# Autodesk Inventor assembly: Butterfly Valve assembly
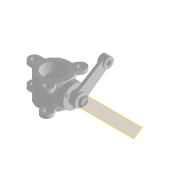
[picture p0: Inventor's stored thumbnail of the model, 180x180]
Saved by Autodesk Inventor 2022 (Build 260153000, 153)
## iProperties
Created: 2019-03
Part Number: Butterfly Valve assembly
Document SubType Name: Assembly
Designer: LENOVO-CADCIM
Author: LENOVO-CADCIM
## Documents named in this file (10)
- D:\PROJECTS_2021\Resources\Tutorial Files\c10_Inv_2022_tut\c10_tut01_Inv\Butterfly Valve\Butterfly Valve assembly.iam
- D:\PROJECTS_2021\Resources\Tutorial Files\c10_Inv_2022_tut\c10_tut01_Inv\Butterfly Valve\Body.ipt
- D:\PROJECTS_2021\Resources\Tutorial Files\c10_Inv_2022_tut\c10_tut01_Inv\Butterfly Valve\Shaft.ipt
- D:\PROJECTS_2021\Resources\Tutorial Files\c10_Inv_2022_tut\c10_tut01_Inv\Butterfly Valve\Retainer.ipt
- D:\PROJECTS_2021\Resources\Tutorial Files\c10_Inv_2022_tut\c10_tut01_Inv\Butterfly Valve\Arm.ipt
- D:\PROJECTS_2021\Resources\Tutorial Files\c10_Inv_2022_tut\c10_tut01_Inv\Butterfly Valve\Plate.ipt
- D:\PROJECTS_2021\Resources\Tutorial Files\c10_Inv_2022_tut\c10_tut01_Inv\Butterfly Valve\scew1.ipt
- D:\PROJECTS_2021\Resources\Tutorial Files\c10_Inv_2022_tut\c10_tut01_Inv\Butterfly Valve\Screw.ipt
- D:\PROJECTS_2021\Resources\Tutorial Files\c10_Inv_2022_tut\c10_tut01_Inv\Butterfly Valve\Parallel key.ipt
- D:\PROJECTS_2021\Resources\Tutorial Files\c10_Inv_2022_tut\c10_tut01_Inv\Butterfly Valve\Nut.ipt
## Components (12 placed, 9 different names)
1. Body:1 — Insert:1, Insert:2, Mate:1, Angle:4, Angle:5
2. Shaft:1 — Insert:1, Insert:3, Insert:4, Mate:3, Insert:11, Angle:5
3. Retainer:1 — Insert:2, Mate:1, Insert:7, Insert:8, Insert:9, Insert:10
4. Arm:1 — Insert:10, Mate:2, Flush:1
5. Plate:1 — Insert:3, Insert:4, Insert:5, Insert:6
6. scew1:1 — Insert:5
7. scew1:2 — Insert:6
8. Screw:1 — Insert:7
9. Screw:2 — Insert:8
10. Screw:3 — Insert:9
11. Parallel key:1 — Mate:2, Mate:3, Flush:1
12. Nut:1 — Insert:11, Angle:4
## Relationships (17: Insert 11, Mate 3, Angle 2, Flush 1)
- Insert:1: Body:1 ↔ Shaft:1
- Insert:2: Body:1 ↔ Retainer:1
- Mate:1: Body:1 ↔ Retainer:1
- Insert:3: Shaft:1 ↔ Plate:1
- Insert:4: Shaft:1 ↔ Plate:1
- Insert:5: Plate:1 ↔ scew1:1
- Insert:6: Plate:1 ↔ scew1:2
- Insert:7: Retainer:1 ↔ Screw:1
- Insert:8: Retainer:1 ↔ Screw:2
- Insert:9: Retainer:1 ↔ Screw:3
- Insert:10: Retainer:1 ↔ Arm:1
- Mate:2: Arm:1 ↔ Parallel key:1
- Mate:3: Shaft:1 ↔ Parallel key:1
- Flush:1: Arm:1 ↔ Parallel key:1
- Insert:11: Shaft:1 ↔ Nut:1
- Angle:4: Body:1 ↔ Nut:1
- Angle:5: Body:1 ↔ Shaft:1
